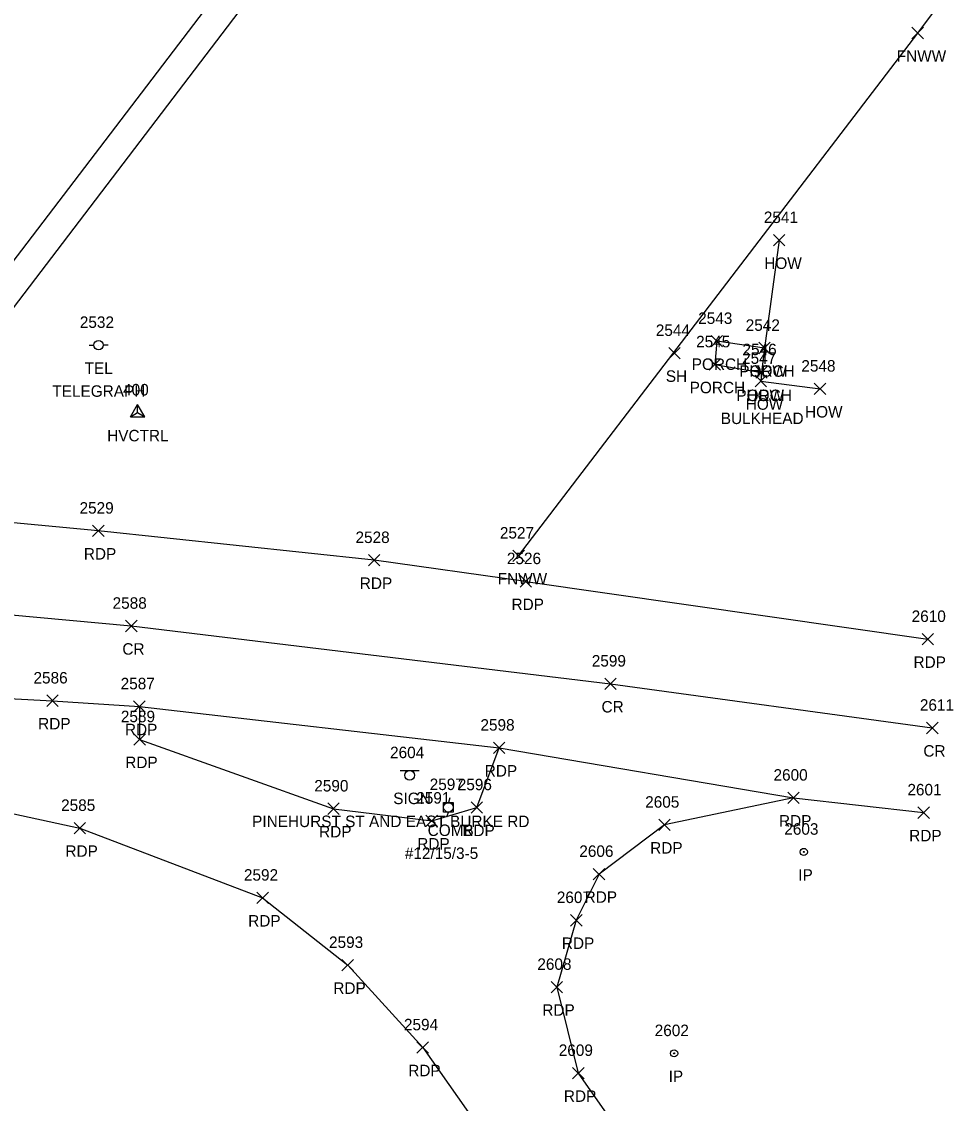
# Model space of a CAD drawing. Extents: x 1767353 to 1772625, y 740790 to 747702.
# Drawn here: x 1772288.6 to 1772451.2, y 747316.1 to 747504.6 of the extents above; entities that cross this region are included whole.
import ezdxf

# ---------------------------------------------------------------- set-up
doc = ezdxf.new("R2010")
doc.units = 0
for name, color, linetype in [('C_A', 7, 'Continuous'), ('C_I', 7, 'Continuous'), ('CPSM', 7, 'Continuous'), ('L_A', 7, 'Continuous'), ('L_C', 7, 'Continuous'), ('L_I', 7, 'Continuous'), ('L_TIC', 7, 'Continuous'), ('LBC', 7, 'Continuous'), ('LBF', 7, 'Continuous'), ('LFNC', 7, 'Continuous'), ('M_A', 7, 'Continuous'), ('M_I', 7, 'Continuous'), ('MPIR', 7, 'Continuous'), ('P_A', 7, 'Continuous'), ('P_I', 7, 'Continuous'), ('P_TIC', 7, 'Continuous'), ('PET', 7, 'Continuous'), ('PRC', 7, 'Continuous'), ('RR', 7, 'Continuous'), ('S_A', 7, 'Continuous'), ('S_C', 7, 'Continuous'), ('S_I', 7, 'Continuous'), ('SSGN', 7, 'Continuous'), ('U_A', 7, 'Continuous'), ('U_C', 7, 'Continuous'), ('U_I', 7, 'Continuous'), ('UP', 7, 'Continuous')]:
    doc.layers.add(name, color=color, linetype=linetype)

msp = doc.modelspace()

# ---------------------------------------------------------------- linework, layer by layer
at = {"layer": 'CPSM'}
for p, q in [((1772307.55, 747435.73), (1772308.8, 747437.9)), ((1772307.55, 747435.73), (1772308.8, 747437.9)), ((1772307.55, 747435.73), (1772308.8, 747437.9)), ((1772307.55, 747435.73), (1772308.8, 747437.9)), ((1772307.55, 747435.73), (1772308.8, 747436.46)), ((1772307.55, 747435.73), (1772308.8, 747436.46)), ((1772307.55, 747435.73), (1772308.8, 747436.46)), ((1772307.55, 747435.73), (1772308.8, 747436.46)), ((1772310.05, 747435.73), (1772308.8, 747437.9)), ((1772308.8, 747436.46), (1772308.8, 747437.9)), ((1772310.05, 747435.73), (1772308.8, 747437.9)), ((1772308.8, 747436.46), (1772308.8, 747437.9)), ((1772310.05, 747435.73), (1772308.8, 747437.9)), ((1772308.8, 747436.46), (1772308.8, 747437.9)), ((1772310.05, 747435.73), (1772308.8, 747437.9)), ((1772308.8, 747436.46), (1772308.8, 747437.9)), ((1772308.8, 747436.46), (1772308.8, 747436.46)), ((1772308.8, 747436.46), (1772310.05, 747435.73)), ((1772308.8, 747436.46), (1772308.8, 747436.46)), ((1772308.8, 747436.46), (1772310.05, 747435.73)), ((1772308.8, 747436.46), (1772308.8, 747436.46)), ((1772308.8, 747436.46), (1772310.05, 747435.73)), ((1772308.8, 747436.46), (1772308.8, 747436.46)), ((1772308.8, 747436.46), (1772310.05, 747435.73)), ((1772307.55, 747435.73), (1772310.05, 747435.73)), ((1772307.55, 747435.73), (1772310.05, 747435.73)), ((1772307.55, 747435.73), (1772310.05, 747435.73)), ((1772307.55, 747435.73), (1772310.05, 747435.73))]:
    msp.add_line(p, q, dxfattribs=at)
at = {"layer": 'L_TIC'}
for points in [[(1772443.65, 747501.58), (1772445.65, 747503.58)], [(1772445.65, 747501.58), (1772443.65, 747503.58)], [(1772419.54, 747465.49), (1772421.54, 747467.49)], [(1772421.54, 747465.49), (1772419.54, 747467.49)], [(1772408.68, 747447.91), (1772410.68, 747449.91)], [(1772410.68, 747447.91), (1772408.68, 747449.91)], [(1772401.3, 747445.82), (1772403.3, 747447.82)], [(1772403.3, 747445.82), (1772401.3, 747447.82)], [(1772416.96, 747446.71), (1772418.96, 747448.71)], [(1772418.96, 747446.71), (1772416.96, 747448.71)], [(1772416.96, 747446.71), (1772418.96, 747448.71)], [(1772418.96, 747446.71), (1772416.96, 747448.71)], [(1772408.32, 747443.84), (1772410.32, 747445.84)], [(1772410.32, 747443.84), (1772408.32, 747445.84)], [(1772416.46, 747442.47), (1772418.46, 747444.47)], [(1772418.46, 747442.47), (1772416.46, 747444.47)], [(1772416.46, 747442.47), (1772418.46, 747444.47)], [(1772418.46, 747442.47), (1772416.46, 747444.47)], [(1772416.32, 747440.96), (1772418.32, 747442.96)], [(1772418.32, 747440.96), (1772416.32, 747442.96)], [(1772426.65, 747439.61), (1772428.65, 747441.61)], [(1772428.65, 747439.61), (1772426.65, 747441.61)], [(1772374.15, 747410.53), (1772376.15, 747412.53)], [(1772376.15, 747410.53), (1772374.15, 747412.53)]]:
    msp.add_lwpolyline(points, dxfattribs=at)
at = {"layer": 'LBC'}
msp.add_lwpolyline([(1772420.54, 747466.49), (1772417.96, 747447.71), (1772417.46, 747443.47), (1772417.32, 747441.96), (1772427.65, 747440.61)], dxfattribs=at)
at = {"layer": 'LBF'}
msp.add_lwpolyline([(1772417.96, 747447.71), (1772409.68, 747448.91), (1772409.32, 747444.84), (1772417.46, 747443.47)], dxfattribs=at)
at = {"layer": 'LFNC'}
msp.add_lwpolyline([(1772375.15, 747411.53), (1772444.65, 747502.58), (1772497.04, 747572.52)], dxfattribs=at)
at = {"layer": 'MPIR'}
for centre, radius in [((1772424.81, 747359.94), 0.625), ((1772424.81, 747359.94), 0.0833), ((1772402.23, 747324.86), 0.625), ((1772402.23, 747324.86), 0.0833)]:
    msp.add_circle(centre, radius, dxfattribs=at)
at = {"layer": 'P_TIC'}
for points in [[(1772300.95, 747414.87), (1772302.95, 747416.87)], [(1772302.95, 747414.87), (1772300.95, 747416.87)], [(1772349, 747409.75), (1772351, 747411.75)], [(1772351, 747409.75), (1772349, 747411.75)], [(1772375.42, 747406.07), (1772377.42, 747408.07)], [(1772377.42, 747406.07), (1772375.42, 747408.07)], [(1772375.42, 747406.07), (1772377.42, 747408.07)], [(1772377.42, 747406.07), (1772375.42, 747408.07)], [(1772306.7, 747398.3), (1772308.7, 747400.3)], [(1772308.7, 747398.3), (1772306.7, 747400.3)], [(1772445.43, 747396), (1772447.43, 747398)], [(1772447.43, 747396), (1772445.43, 747398)], [(1772390.16, 747388.23), (1772392.16, 747390.23)], [(1772392.16, 747388.23), (1772390.16, 747390.23)], [(1772292.98, 747385.28), (1772294.98, 747387.28)], [(1772294.98, 747385.28), (1772292.98, 747387.28)], [(1772308.1, 747384.27), (1772310.1, 747386.27)], [(1772310.1, 747384.27), (1772308.1, 747386.27)], [(1772308.1, 747384.27), (1772310.1, 747386.27)], [(1772310.1, 747384.27), (1772308.1, 747386.27)], [(1772446.2, 747380.54), (1772448.2, 747382.54)], [(1772448.2, 747380.54), (1772446.2, 747382.54)], [(1772308.15, 747378.54), (1772310.15, 747380.54)], [(1772310.15, 747378.54), (1772308.15, 747380.54)], [(1772370.76, 747377.07), (1772372.76, 747379.07)], [(1772372.76, 747377.07), (1772370.76, 747379.07)], [(1772370.76, 747377.07), (1772372.76, 747379.07)], [(1772372.76, 747377.07), (1772370.76, 747379.07)], [(1772422.02, 747368.36), (1772424.02, 747370.36)], [(1772424.02, 747368.36), (1772422.02, 747370.36)], [(1772422.02, 747368.36), (1772424.02, 747370.36)], [(1772424.02, 747368.36), (1772422.02, 747370.36)], [(1772341.91, 747366.47), (1772343.91, 747368.47)], [(1772343.91, 747366.47), (1772341.91, 747368.47)], [(1772366.86, 747366.69), (1772368.86, 747368.69)], [(1772368.86, 747366.69), (1772366.86, 747368.69)], [(1772444.68, 747365.79), (1772446.68, 747367.79)], [(1772446.68, 747365.79), (1772444.68, 747367.79)], [(1772297.73, 747363.09), (1772299.73, 747365.09)], [(1772299.73, 747363.09), (1772297.73, 747365.09)], [(1772359.01, 747364.36), (1772361.01, 747366.36)], [(1772361.01, 747364.36), (1772359.01, 747366.36)], [(1772399.57, 747363.65), (1772401.57, 747365.65)], [(1772401.57, 747363.65), (1772399.57, 747365.65)], [(1772388.16, 747355.08), (1772390.16, 747357.08)], [(1772390.16, 747355.08), (1772388.16, 747357.08)], [(1772329.57, 747350.94), (1772331.57, 747352.94)], [(1772331.57, 747350.94), (1772329.57, 747352.94)], [(1772384.19, 747347.04), (1772386.19, 747349.04)], [(1772386.19, 747347.04), (1772384.19, 747349.04)], [(1772344.39, 747339.22), (1772346.39, 747341.22)], [(1772346.39, 747339.22), (1772344.39, 747341.22)], [(1772380.79, 747335.4), (1772382.79, 747337.4)], [(1772382.79, 747335.4), (1772380.79, 747337.4)], [(1772357.44, 747324.87), (1772359.44, 747326.87)], [(1772359.44, 747324.87), (1772357.44, 747326.87)], [(1772384.54, 747320.41), (1772386.54, 747322.41)], [(1772386.54, 747320.41), (1772384.54, 747322.41)]]:
    msp.add_lwpolyline(points, dxfattribs=at)
at = {"layer": 'PET'}
for points in [[(1772376.42, 747407.07), (1772350, 747410.75), (1772301.95, 747415.87), (1772276.65, 747418.25), (1772266.51, 747419.8), (1772250.63, 747422.36), (1772220.33, 747425.37), (1772188.24, 747427.11), (1772161.2, 747427.19), (1772126.06, 747423.68), (1772087.39, 747418.44)], [(1772376.42, 747407.07), (1772446.43, 747397)], [(1772080.59, 747381.74), (1772124.7, 747390.05), (1772167.27, 747392.45), (1772191.1, 747392.31), (1772220.01, 747390.33), (1772248.49, 747388.68), (1772293.98, 747386.28), (1772309.1, 747385.27), (1772371.76, 747378.07), (1772423.02, 747369.36), (1772445.68, 747366.79)], [(1772248.49, 747388.68), (1772247.85, 747380.52), (1772247.94, 747371.83), (1772271.67, 747369.93), (1772298.73, 747364.09), (1772330.57, 747351.94), (1772345.39, 747340.22), (1772358.44, 747325.87), (1772369.01, 747310.86), (1772376.2, 747299.13), (1772388.77, 747279.71), (1772413.33, 747239.35), (1772432.47, 747203.55), (1772442.3, 747177.42), (1772448.21, 747146.38), (1772450.04, 747126.57), (1772447.64, 747094.15), (1772439.71, 747049.07), (1772429.11, 746997.48), (1772420.36, 746945.09), (1772413.46, 746884.56)], [(1772309.1, 747385.27), (1772309.15, 747379.54), (1772342.91, 747367.47), (1772360.01, 747365.36), (1772367.86, 747367.69), (1772371.76, 747378.07)], [(1772423.02, 747369.36), (1772400.57, 747364.65), (1772389.16, 747356.08), (1772385.19, 747348.04), (1772381.79, 747336.4), (1772385.54, 747321.41), (1772406.08, 747292.03), (1772418.62, 747273.41), (1772432.37, 747251.33), (1772453.8, 747211.7), (1772464.48, 747185.04), (1772470.88, 747155.37), (1772474.1, 747125.56), (1772472.24, 747090.44), (1772463.23, 747043.99), (1772452.34, 746992.54), (1772444.15, 746940.14), (1772438.17, 746885.19)]]:
    msp.add_lwpolyline(points, dxfattribs=at)
at = {"layer": 'PRC'}
msp.add_lwpolyline([(1772025.6, 747384.96), (1772051.83, 747392.67), (1772087.04, 747400.73), (1772128.86, 747406.79), (1772195.18, 747408.55), (1772233.07, 747406.2), (1772307.7, 747399.3), (1772391.16, 747389.23), (1772447.2, 747381.54)], dxfattribs=at)
at = {"layer": 'RR'}
for points in [[(1771960.76, 746895.46), (1771976.57, 746936.04), (1771991.76, 746972.7), (1772003.71, 747000.43), (1772025.97, 747048.7), (1772044.45, 747086.9), (1772066.42, 747128.97), (1772087.05, 747166.47), (1772110.84, 747207.58), (1772133.43, 747244.66), (1772156.72, 747281.04), (1772175.9, 747310.14), (1772194.46, 747336.8), (1772219.05, 747370.3), (1772232.59, 747389.89), (1772256.2, 747421.67), (1772277.77, 747450.57), (1772416.44, 747632.57), (1772465.26, 747696.66)], [(1771963.49, 746888.34), (1771980.41, 746932.18), (1771994.59, 746967.04), (1772007.72, 746997.13), (1772029.49, 747045.02), (1772048.72, 747084.09), (1772070.77, 747126.16), (1772091.38, 747163.68), (1772115.23, 747205.31), (1772138.09, 747242.79), (1772160.69, 747278.1), (1772180.23, 747307.44), (1772199.65, 747335.62), (1772224.35, 747370.12), (1772238.38, 747389.48), (1772261.28, 747420.38), (1772281.38, 747447.15), (1772420.28, 747629.6), (1772469.26, 747693.79)]]:
    msp.add_lwpolyline(points, dxfattribs=at)
at = {"layer": 'SSGN'}
for p, q in [((1772354.52, 747374.12), (1772357.85, 747374.12)), ((1772356.17, 747373.29), (1772356.17, 747373.29))]:
    msp.add_line(p, q, dxfattribs=at)
msp.add_circle((1772356.17, 747373.29), 0.833, dxfattribs=at)
at = {"layer": 'UP'}
for p, q in [((1772300.33, 747448.22), (1772301.16, 747448.22)), ((1772301.99, 747448.22), (1772301.99, 747448.22)), ((1772303.66, 747448.22), (1772302.82, 747448.22)), ((1772302.82, 747448.22), (1772302.82, 747448.22)), ((1772303.66, 747448.22), (1772303.66, 747448.22)), ((1772362.09, 747366.88), (1772362.09, 747368.55)), ((1772362.09, 747368.55), (1772363.75, 747368.55)), ((1772363.17, 747369.38), (1772362.92, 747368.55)), ((1772363.75, 747368.55), (1772363.75, 747366.88)), ((1772363.75, 747366.88), (1772362.09, 747366.88)), ((1772362.67, 747366.05), (1772362.92, 747366.88)), ((1772362.92, 747367.72), (1772362.92, 747367.72))]:
    msp.add_line(p, q, dxfattribs=at)
for centre in [(1772301.99, 747448.22), (1772362.92, 747367.72)]:
    msp.add_circle(centre, 0.833, dxfattribs=at)

# ---------------------------------------------------------------- texts
at = {"layer": 'C_A'}
msp.add_text('HVCTRL', height=2, dxfattribs=at).set_placement((1772303.49, 747431.46))
msp.add_text('HVCTRL', height=2, dxfattribs=at).set_placement((1772303.49, 747431.46))
msp.add_text('HVCTRL', height=2, dxfattribs=at).set_placement((1772303.49, 747431.46))
msp.add_text('HVCTRL', height=2, dxfattribs=at).set_placement((1772303.49, 747431.46))
at = {"layer": 'C_I'}
msp.add_text('400', height=2, dxfattribs=at).set_placement((1772306.27, 747439.46))
msp.add_text('400', height=2, dxfattribs=at).set_placement((1772306.27, 747439.46))
msp.add_text('400', height=2, dxfattribs=at).set_placement((1772306.27, 747439.46))
msp.add_text('400', height=2, dxfattribs=at).set_placement((1772306.27, 747439.46))
at = {"layer": 'L_A'}
for s, p in [('FNWW', (1772441, 747497.58)), ('HOW', (1772417.93, 747461.49)), ('PORCH', (1772405.3, 747443.91)), ('SH', (1772400.79, 747441.82)), ('PORCH', (1772413.58, 747442.71)), ('HOW', (1772415.34, 747442.71)), ('PORCH', (1772404.94, 747439.84)), ('PORCH', (1772413.08, 747438.47)), ('HOW', (1772414.84, 747438.47)), ('HOW', (1772414.71, 747436.96)), ('HOW', (1772425.03, 747435.61)), ('FNWW', (1772371.5, 747406.53))]:
    msp.add_text(s, height=2, dxfattribs=at).set_placement(p)
at = {"layer": 'L_C'}
msp.add_text('BULKHEAD', height=2, dxfattribs=at).set_placement((1772410.36, 747434.47))
at = {"layer": 'L_I'}
for s, p in [('2541', (1772417.85, 747469.49)), ('2543', (1772406.42, 747451.91)), ('2544', (1772399.04, 747449.82)), ('2542', (1772414.7, 747450.71)), ('2542', (1772414.7, 747450.71)), ('2545', (1772406.06, 747447.84)), ('2546', (1772414.14, 747446.47)), ('2546', (1772414.14, 747446.47)), ('2547', (1772414.06, 747444.96)), ('2548', (1772424.39, 747443.61)), ('2527', (1772371.89, 747414.53))]:
    msp.add_text(s, height=2, dxfattribs=at).set_placement(p)
at = {"layer": 'M_A'}
for p in [(1772423.86, 747354.94), (1772401.28, 747319.86)]:
    msp.add_text('IP', height=2, dxfattribs=at).set_placement(p)
at = {"layer": 'M_I'}
for s, p in [('2603', (1772421.42, 747362.94)), ('2602', (1772398.85, 747327.86))]:
    msp.add_text(s, height=2, dxfattribs=at).set_placement(p)
at = {"layer": 'P_A'}
for s, p in [('RDP', (1772299.43, 747410.87)), ('RDP', (1772347.49, 747405.75)), ('RDP', (1772373.91, 747402.07)), ('RDP', (1772373.91, 747402.07)), ('CR', (1772306.14, 747394.3)), ('RDP', (1772443.92, 747392)), ('CR', (1772389.59, 747384.23)), ('RDP', (1772291.47, 747381.28)), ('RDP', (1772306.59, 747380.27)), ('RDP', (1772306.59, 747380.27)), ('CR', (1772445.64, 747376.54)), ('RDP', (1772306.64, 747374.54)), ('RDP', (1772369.25, 747373.07)), ('RDP', (1772369.25, 747373.07)), ('RDP', (1772365.35, 747362.69)), ('RDP', (1772420.5, 747364.36)), ('RDP', (1772420.5, 747364.36)), ('RDP', (1772340.4, 747362.47)), ('RDP', (1772443.17, 747361.79)), ('RDP', (1772296.22, 747359.09)), ('RDP', (1772357.5, 747360.36)), ('RDP', (1772398.06, 747359.65)), ('RDP', (1772386.65, 747351.08)), ('RDP', (1772328.05, 747346.94)), ('RDP', (1772382.68, 747343.04)), ('RDP', (1772342.88, 747335.22)), ('RDP', (1772379.28, 747331.4)), ('RDP', (1772355.93, 747320.87)), ('RDP', (1772383.03, 747316.41))]:
    msp.add_text(s, height=2, dxfattribs=at).set_placement(p)
at = {"layer": 'P_I'}
for s, p in [('2529', (1772298.68, 747418.87)), ('2528', (1772346.74, 747413.75)), ('2526', (1772373.11, 747410.07)), ('2526', (1772373.11, 747410.07)), ('2588', (1772304.44, 747402.3)), ('2610', (1772443.6, 747400)), ('2599', (1772387.89, 747392.23)), ('2586', (1772290.66, 747389.28)), ('2587', (1772305.84, 747388.27)), ('2587', (1772305.84, 747388.27)), ('2611', (1772445.03, 747384.54)), ('2589', (1772305.88, 747382.54)), ('2598', (1772368.5, 747381.07)), ('2598', (1772368.5, 747381.07)), ('2600', (1772419.54, 747372.36)), ('2600', (1772419.54, 747372.36)), ('2590', (1772339.56, 747370.47)), ('2596', (1772364.55, 747370.69)), ('2591', (1772357.32, 747368.36)), ('2601', (1772442.86, 747369.79)), ('2585', (1772295.47, 747367.09)), ('2605', (1772397.19, 747367.65)), ('2606', (1772385.72, 747359.08)), ('2592', (1772327.31, 747354.94)), ('2607', (1772381.8, 747351.04)), ('2593', (1772342.13, 747343.22)), ('2608', (1772378.41, 747339.4)), ('2594', (1772355.18, 747328.87)), ('2609', (1772382.14, 747324.41))]:
    msp.add_text(s, height=2, dxfattribs=at).set_placement(p)
at = {"layer": 'S_A'}
msp.add_text('SIGN', height=2, dxfattribs=at).set_placement((1772353.31, 747368.27))
at = {"layer": 'S_C'}
msp.add_text('PINEHURST ST AND EAST BURKE RD', height=2, dxfattribs=at).set_placement((1772328.74, 747364.27))
at = {"layer": 'S_I'}
msp.add_text('2604', height=2, dxfattribs=at).set_placement((1772352.76, 747376.27))
at = {"layer": 'U_A'}
for s, p in [('TEL', (1772299.55, 747443.22)), ('COMB', (1772359.31, 747362.72))]:
    msp.add_text(s, height=2, dxfattribs=at).set_placement(p)
at = {"layer": 'U_C'}
for s, p in [('TELEGRAPH', (1772293.94, 747439.22)), ('#12/15/3-5', (1772355.33, 747358.72))]:
    msp.add_text(s, height=2, dxfattribs=at).set_placement(p)
at = {"layer": 'U_I'}
for s, p in [('2532', (1772298.73, 747451.22)), ('2597', (1772359.66, 747370.72))]:
    msp.add_text(s, height=2, dxfattribs=at).set_placement(p)

doc.saveas('drawing.dxf')
